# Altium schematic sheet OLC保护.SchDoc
size A4
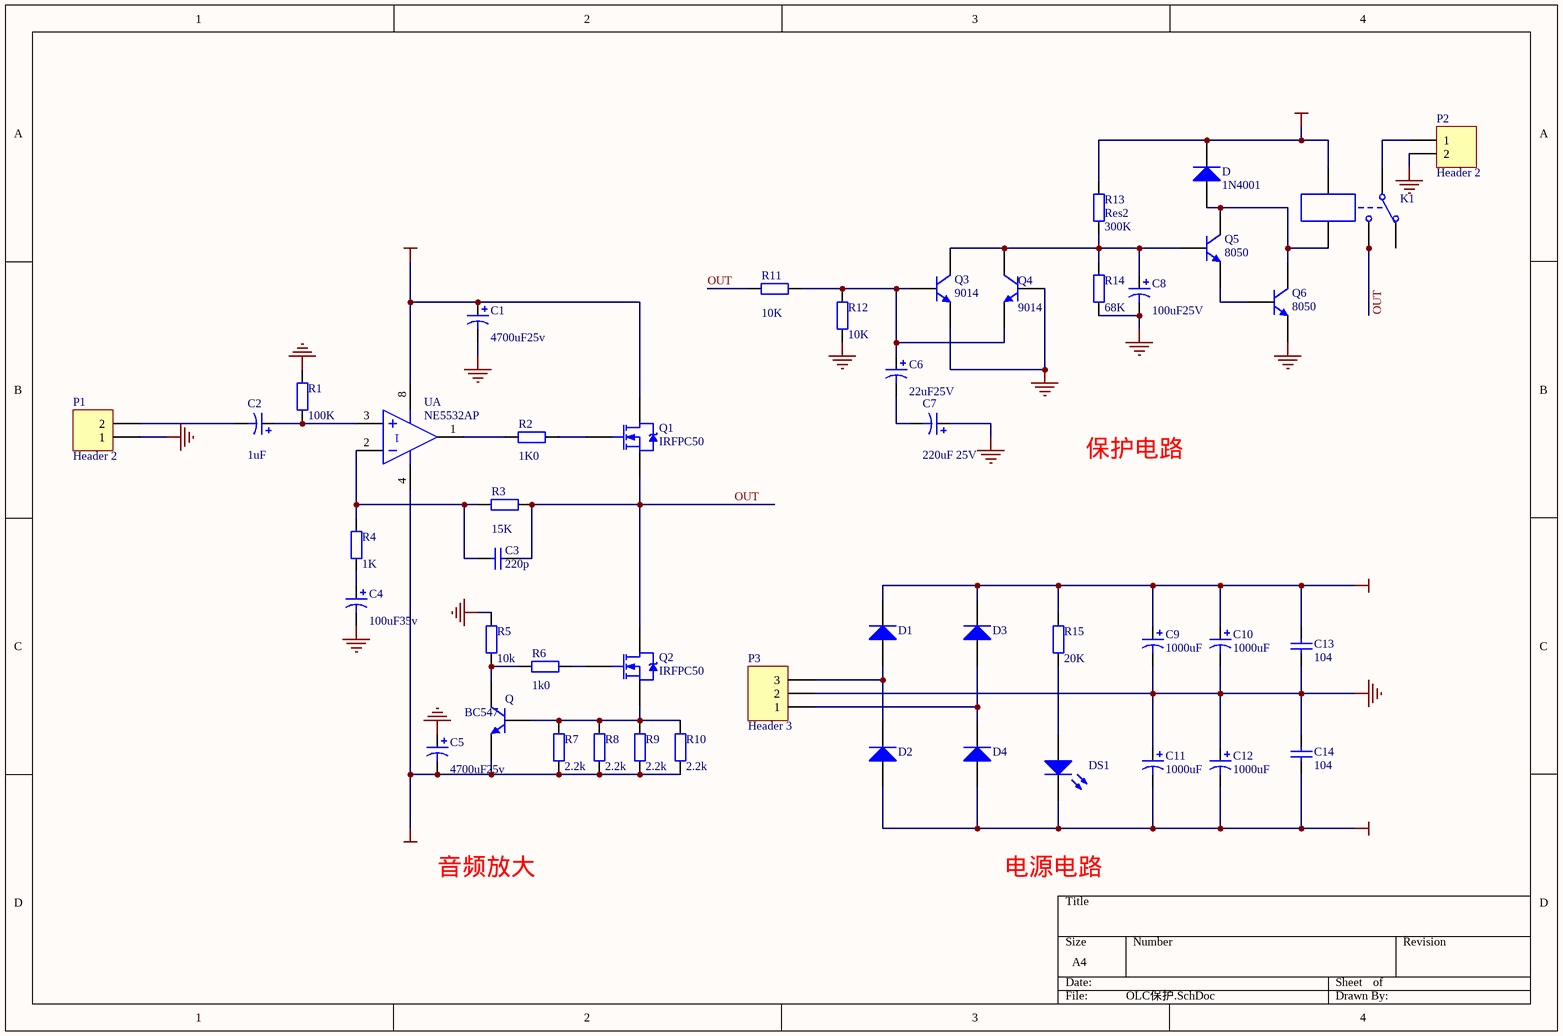
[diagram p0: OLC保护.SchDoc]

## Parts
C1  value 4700uF25v  [RB7.6-15]  (hidden comment: Cap Pol1)
C2  value 1uF  [RB7.6-15]  (hidden comment: Cap Pol1)
C3  value 220p  [RAD-0.3]  (hidden comment: Cap)
C4  value 100uF35v  [RB7.6-15]  (hidden comment: Cap Pol1)
C5  value 4700uF25v  [RB7.6-15]  (hidden comment: Cap Pol1)
C6  value 22uF25V  [RB7.6-15]  (hidden comment: Cap Pol1)
C7  value 220uF 25V  [RB7.6-15]  (hidden comment: Cap Pol1)
C8  value 100uF25V  [RB7.6-15]  (hidden comment: Cap Pol1)
C9  value 1000uF  [RB7.6-15]  (hidden comment: Cap Pol1)
C10  value 1000uF  [RB7.6-15]  (hidden comment: Cap Pol1)
C11  value 1000uF  [RB7.6-15]  (hidden comment: Cap Pol1)
C12  value 1000uF  [RB7.6-15]  (hidden comment: Cap Pol1)
C13  value 104  [RAD-0.3]  (hidden comment: Cap)
C14  value 104  [RAD-0.3]  (hidden comment: Cap)
D  1N4001  [DIO10.46-5.3x2.8]
D1  Diode 1N914  [DIO7.1-3.9x1.9]  (value not drawn)
D2  Diode 1N914  [DIO7.1-3.9x1.9]  (value not drawn)
D3  Diode 1N914  [DIO7.1-3.9x1.9]  (value not drawn)
D4  Diode 1N914  [DIO7.1-3.9x1.9]  (value not drawn)
DS1  LED0  [LED-0]  (value not drawn)
K1  Relay-SPDT  [DIP-P5/X1.65]  (value not drawn)
P1  Header 2  [HDR1X2]
P2  Header 2  [HDR1X2]
P3  Header 3  [HDR1X3]
Q  BC547  [BCY-W3/E4]
Q1  IRFPC50  [TO-247AC]
Q2  IRFPC50  [TO-247AC]
Q3  9014  [BCY-W3/E4]
Q4  9014  [BCY-W3/E4]
Q5  8050  [BCY-W3/E4]
Q6  8050  [BCY-W3/E4]
R1  value 100K  [AXIAL-0.4]  (hidden comment: Res2)
R2  value 1K0  [AXIAL-0.4]  (hidden comment: Res2)
R3  value 15K  [AXIAL-0.4]  (hidden comment: Res2)
R4  value 1K  [AXIAL-0.4]  (hidden comment: Res2)
R5  value 10k  [AXIAL-0.4]  (hidden comment: Res2)
R6  value 1k0  [AXIAL-0.4]  (hidden comment: Res2)
R7  value 2.2k  [AXIAL-0.4]  (hidden comment: Res2)
R8  value 2.2k  [AXIAL-0.4]  (hidden comment: Res2)
R9  value 2.2k  [AXIAL-0.4]  (hidden comment: Res2)
R10  value 2.2k  [AXIAL-0.4]  (hidden comment: Res2)
R11  value 10K  [AXIAL-0.4]  (hidden comment: Res2)
R12  value 10K  [AXIAL-0.4]  (hidden comment: Res2)
R13  Res2  value 300K  [AXIAL-0.4]
R14  value 68K  [AXIAL-0.4]  (hidden comment: Res2)
R15  value 20K  [AXIAL-0.4]  (hidden comment: Res2)
U  NE5532AP  [P008]  (part A of 2)

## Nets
+12V: C1.1 C9.1 C10.1 C13.1 D.2(K) D1.2(K) D3.2(K) K1.4 Q1.2(D) R13.1 R15.2 U.8(V+)
-12V: C5.2 C11.2 C12.2 C14.1 D2.1(A) D4.1(A) DS1.2(K) Q.1(E) R7.1 R8.1 R9.1 R10.1 U.4(v-)
GND: C1.2 C4.2 C5.1 C7.1 C8.2 C9.2 C10.2 C11.1 C12.1 C13.2 C14.2 P1.1 P2.2 P3.2 Q3.1(E) Q4.2(B) Q6.1(E) R1.2 R5.1 R12.2 R14.2
OUT: C3.2 K1.3 Q1.3(S) Q2.2(D) R3.2 R11.2
NetC2_1: C2.1 R1.1 U.3(IN+)
NetC2_2: C2.2 P1.2
NetC3_1: C3.1 R3.1 R4.2 U.2(IN-)
NetC4_1: C4.1 R4.1
NetC6_1: C6.1 Q3.2(B) Q4.1(E) R11.1 R12.1
NetC6_2: C6.2 C7.2
NetC8_1: C8.1 Q3.3(C) Q4.3(C) Q5.2(B) R13.2 R14.1
NetD1_1: D1.1(A) D2.2(K) P3.3
NetD3_1: D3.1(A) D4.2(K) P3.1
NetD_1: D.1(A) K1.5 Q5.3(C) Q6.3(C)
NetDS1_1: DS1.1(A) R15.1
NetK1_1: K1.1 P2.1
NetQ1_1: Q1.1(G) R2.2
NetQ2_1: Q2.1(G) R6.2
NetQ5_1: Q5.1(E) Q6.2(B)
NetQ_2: Q.2(B) Q2.3(S) R7.2 R8.2 R9.2 R10.2
NetQ_3: Q.3(C) R5.2 R6.1
NetR2_1: R2.1 U.1(OUT)

Not connected (* = marked no-connect by the designer): K1 2

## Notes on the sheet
- 保护电路
- 音频放大
- 电源电路

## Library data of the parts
C1 C2 C4-C12 = Cap Pol1: Polarized Capacitor (Radial)
C3 C13 C14 = Cap: Capacitor
D = Diode 1N4001: 1 Amp General Purpose Rectifier
D1-D4 = Diode 1N914: High Conductance Fast Diode
DS1 = LED0: Typical INFRARED GaAs LED
K1 = Relay-SPDT: Single-Pole Dual-Throw Relay
P1 P2 = Header 2: Header, 2-Pin
P3 = Header 3: Header, 3-Pin
Q Q3-Q6 = 2N3904: NPN General Purpose Amplifier
Q1 Q2 = IRFPC50: HEXFET Power MOSFET; Note: Pin 2 is electrically connected to the Heatsink (4).
R1-R15 = Res2: Resistor
U = NE5532AP: Dual Low-Noise Operational Amplifier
